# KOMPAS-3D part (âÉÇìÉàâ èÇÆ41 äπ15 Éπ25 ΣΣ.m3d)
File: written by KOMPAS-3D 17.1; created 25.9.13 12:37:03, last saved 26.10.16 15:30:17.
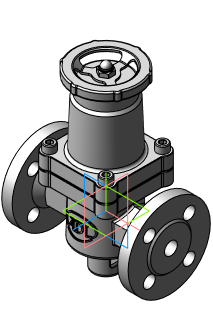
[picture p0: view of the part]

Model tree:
1. Операция без истории:4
